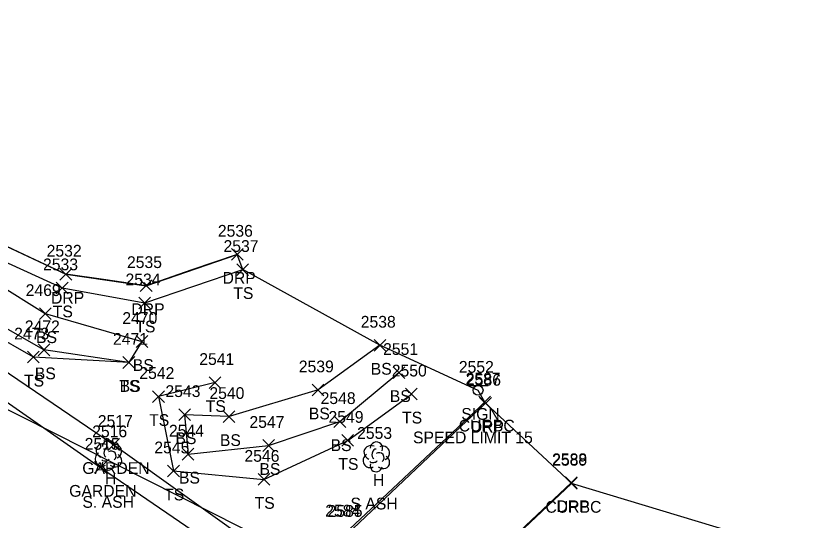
# Model space of a CAD drawing. Extents: x 1623612 to 1625808, y 621345 to 627748.
# Drawn here: x 1624561.2 to 1624694.8, y 626611.6 to 626697.4 of the extents above; entities that cross this region are included whole.
import ezdxf

# ---------------------------------------------------------------- set-up
doc = ezdxf.new("R2010")
doc.units = 0
for name, color, linetype in [('DCP', 7, 'Continuous'), ('L_A', 7, 'Continuous'), ('L_C', 7, 'Continuous'), ('L_I', 7, 'Continuous'), ('L_TIC', 7, 'Continuous'), ('LAPB', 7, 'Continuous'), ('LELB', 7, 'Continuous'), ('LSOGP', 7, 'Continuous'), ('LTD', 7, 'Continuous'), ('R_A', 7, 'Continuous'), ('R_I', 7, 'Continuous'), ('R_TIC', 7, 'Continuous'), ('RC', 7, 'Continuous'), ('RDP', 7, 'Continuous'), ('S_A', 7, 'Continuous'), ('S_C', 7, 'Continuous'), ('S_I', 7, 'Continuous'), ('SSGN', 7, 'Continuous')]:
    doc.layers.add(name, color=color, linetype=linetype)

msp = doc.modelspace()

# ---------------------------------------------------------------- linework, layer by layer
at = {"layer": 'DCP'}
msp.add_lwpolyline([(1624498.55, 626661.39), (1624711.06, 626553.97)], dxfattribs=at)
at = {"layer": 'L_TIC'}
for points in [[(1624598.82, 626653.21), (1624600.82, 626655.21)], [(1624600.82, 626653.21), (1624598.82, 626655.21)], [(1624568.13, 626650.09), (1624570.13, 626652.09)], [(1624570.13, 626650.09), (1624568.13, 626652.09)], [(1624582.16, 626647.53), (1624584.16, 626649.53)], [(1624584.16, 626647.53), (1624582.16, 626649.53)], [(1624565.25, 626645.71), (1624567.25, 626647.71)], [(1624567.25, 626645.71), (1624565.25, 626647.71)], [(1624581.7, 626640.97), (1624583.7, 626642.97)], [(1624583.7, 626640.97), (1624581.7, 626642.97)], [(1624565.04, 626639.55), (1624567.04, 626641.55)], [(1624567.04, 626639.55), (1624565.04, 626641.55)], [(1624622.15, 626640.33), (1624624.15, 626642.33)], [(1624624.15, 626640.33), (1624622.15, 626642.33)], [(1624563.23, 626638.32), (1624565.23, 626640.32)], [(1624565.23, 626638.32), (1624563.23, 626640.32)], [(1624579.46, 626637.41), (1624581.46, 626639.41)], [(1624581.46, 626637.41), (1624579.46, 626639.41)], [(1624579.46, 626637.41), (1624581.46, 626639.41)], [(1624581.46, 626637.41), (1624579.46, 626639.41)], [(1624625.39, 626635.69), (1624627.39, 626637.69)], [(1624627.39, 626635.69), (1624625.39, 626637.69)], [(1624594.13, 626633.99), (1624596.13, 626635.99)], [(1624596.13, 626633.99), (1624594.13, 626635.99)], [(1624611.63, 626632.73), (1624613.63, 626634.73)], [(1624613.63, 626632.73), (1624611.63, 626634.73)], [(1624584.51, 626631.61), (1624586.51, 626633.61)], [(1624586.51, 626631.61), (1624584.51, 626633.61)], [(1624627.51, 626632.03), (1624629.51, 626634.03)], [(1624629.51, 626632.03), (1624627.51, 626634.03)], [(1624588.95, 626628.53), (1624590.95, 626630.53)], [(1624590.95, 626628.53), (1624588.95, 626630.53)], [(1624596.51, 626628.2), (1624598.51, 626630.2)], [(1624598.51, 626628.2), (1624596.51, 626630.2)], [(1624615.33, 626627.34), (1624617.33, 626629.34)], [(1624617.33, 626627.34), (1624615.33, 626629.34)], [(1624576.88, 626623.45), (1624578.88, 626625.45)], [(1624578.88, 626623.45), (1624576.88, 626625.45)], [(1624603.23, 626623.29), (1624605.23, 626625.29)], [(1624605.23, 626623.29), (1624603.23, 626625.29)], [(1624616.68, 626624.15), (1624618.68, 626626.15)], [(1624618.68, 626624.15), (1624616.68, 626626.15)], [(1624589.54, 626621.81), (1624591.54, 626623.81)], [(1624591.54, 626621.81), (1624589.54, 626623.81)], [(1624574.65, 626619.57), (1624576.65, 626621.57)], [(1624576.65, 626619.57), (1624574.65, 626621.57)], [(1624587.06, 626618.95), (1624589.06, 626620.95)], [(1624589.06, 626618.95), (1624587.06, 626620.95)], [(1624602.44, 626617.52), (1624604.44, 626619.52)], [(1624604.44, 626617.52), (1624602.44, 626619.52)]]:
    msp.add_lwpolyline(points, dxfattribs=at)
at = {"layer": 'LAPB'}
for points in [[(1624519.69, 626684.58), (1624523.34, 626715.13), (1624488.42, 626712.03), (1624477.63, 626714.58), (1624464.93, 626721.39), (1624461.33, 626722.07), (1624457.88, 626718.13), (1624464.59, 626710.11), (1624484.4, 626690.25), (1624505.15, 626670.18), (1624528.47, 626653.34), (1624551.05, 626637.75), (1624575.65, 626620.57), (1624601.46, 626602.9)], [(1624519.69, 626684.58), (1624507.55, 626684.52), (1624497.63, 626694.65), (1624492.88, 626695.51), (1624490.14, 626692.13), (1624493.09, 626687.65), (1624508.66, 626674.45), (1624530.54, 626658.21), (1624552.68, 626641.54), (1624577.88, 626624.45), (1624603.7, 626605.97), (1624601.46, 626602.9)]]:
    msp.add_lwpolyline(points, dxfattribs=at)
at = {"layer": 'LELB'}
for points in [[(1624536.67, 626723.2), (1624539.06, 626695.14), (1624541.99, 626679.69), (1624547.43, 626666.77), (1624555.92, 626657.11), (1624569.13, 626651.09), (1624583.16, 626648.53), (1624599.82, 626654.21)], [(1624491.26, 626721.31), (1624492.07, 626719.16), (1624508.82, 626720.47), (1624530.57, 626721.74), (1624534.88, 626694.95), (1624538.16, 626676.05), (1624549.52, 626657.18), (1624566.25, 626646.71), (1624582.7, 626641.97), (1624580.46, 626638.41), (1624566.04, 626640.55), (1624551.55, 626648.76), (1624540.93, 626658.22), (1624533.96, 626671.15), (1624530.07, 626682.34), (1624528.29, 626695.83)], [(1624580.46, 626638.41), (1624564.23, 626639.32), (1624549.58, 626647.72), (1624538.33, 626656.77), (1624530.6, 626670.09), (1624527.19, 626681.4), (1624524.78, 626695.84), (1624523.34, 626715.13)], [(1624623.15, 626641.33), (1624612.63, 626633.73), (1624597.51, 626629.2), (1624589.95, 626629.53), (1624590.54, 626622.81), (1624604.23, 626624.29), (1624616.33, 626628.34), (1624626.39, 626636.69)], [(1624595.13, 626634.99), (1624585.51, 626632.61), (1624588.06, 626619.95), (1624603.44, 626618.52), (1624617.68, 626625.15), (1624628.51, 626633.03)]]:
    msp.add_lwpolyline(points, dxfattribs=at)
at = {"layer": 'LSOGP'}
msp.add_lwpolyline([(1624698.36, 626604.96), (1624655.71, 626617.85), (1624655.68, 626617.95), (1624641.1, 626631.46), (1624640.98, 626631.67), (1624639.83, 626633.66), (1624623.15, 626641.33), (1624599.82, 626654.21), (1624598.91, 626656.8), (1624591.16, 626654.14), (1624583.41, 626651.47), (1624576.58, 626652.44), (1624569.75, 626653.41), (1624563.68, 626656.25), (1624557.62, 626659.09), (1624553.68, 626663.14), (1624549.75, 626667.18), (1624546.93, 626673.49), (1624544.1, 626679.8), (1624539.06, 626695.14), (1624536.67, 626723.2)], dxfattribs=at)
at = {"layer": 'LTD'}
for p, q in [((1624576.98, 626622.69), (1624576.98, 626622.69)), ((1624576.98, 626622.69), (1624576.98, 626622.69)), ((1624622.53, 626622.41), (1624622.53, 626622.41)), ((1624622.53, 626622.41), (1624622.53, 626622.41))]:
    msp.add_line(p, q, dxfattribs=at)
for centre in [(1624577.02, 626624.12), (1624622.57, 626623.84)]:
    msp.add_arc(centre, 1.05, 335.5272, 180.9563, dxfattribs=at)
for centre, major_axis, ratio, start_param, end_param in [((1624576.18, 626623.36), (1.21, -0.51), 0.895232, 1.570796, 4.712389), ((1624576.77, 626623.15), (-0.208, -0.792), 0.645439, 3.141593, 6.283185), ((1624578.02, 626623.27), (-1.14, -0.48), 0.949671, 1.570796, 4.712389), ((1624621.73, 626623.07), (1.21, -0.51), 0.895232, 1.570796, 4.712389), ((1624623.57, 626622.99), (-1.14, -0.48), 0.949671, 1.570796, 4.712389), ((1624575.89, 626621.98), (0.58, -1.04), 0.959034, 3.141593, 6.283185), ((1624577.48, 626622.52), (-0.5, 0.667), 0.989748, 3.141593, 6.283185), ((1624577.98, 626621.86), (-1.09, 0.79), 0.841452, 1.570796, 4.712389), ((1624621.44, 626621.7), (0.58, -1.04), 0.959034, 3.141593, 6.283185), ((1624622.32, 626622.87), (-0.208, -0.792), 0.645439, 3.141593, 6.283185), ((1624623.03, 626622.24), (-0.5, 0.667), 0.989748, 3.141593, 6.283185), ((1624576.98, 626621.19), (0.26, 1.06), 0.942809, 1.570796, 4.712389), ((1624576.52, 626621.94), (-0.625, -0.083), 0.423636, 0, 3.141593), ((1624622.07, 626621.66), (-0.625, -0.083), 0.423636, 0, 3.141593), ((1624623.53, 626621.57), (-1.09, 0.79), 0.841452, 1.570796, 4.712389), ((1624622.53, 626620.91), (0.26, 1.06), 0.942809, 1.570796, 4.712389)]:
    msp.add_ellipse(centre, major_axis=major_axis, ratio=ratio, start_param=start_param, end_param=end_param, dxfattribs=at)
at = {"layer": 'R_TIC'}
for points in [[(1624597.91, 626655.8), (1624599.91, 626657.8)], [(1624599.91, 626655.8), (1624597.91, 626657.8)], [(1624568.75, 626652.41), (1624570.75, 626654.41)], [(1624570.75, 626652.41), (1624568.75, 626654.41)], [(1624582.41, 626650.47), (1624584.41, 626652.47)], [(1624584.41, 626650.47), (1624582.41, 626652.47)], [(1624639.98, 626630.67), (1624641.98, 626632.67)], [(1624641.98, 626630.67), (1624639.98, 626632.67)], [(1624640.1, 626630.46), (1624642.1, 626632.46)], [(1624642.1, 626630.46), (1624640.1, 626632.46)], [(1624654.68, 626616.95), (1624656.68, 626618.95)], [(1624656.68, 626616.95), (1624654.68, 626618.95)], [(1624654.71, 626616.85), (1624656.71, 626618.85)], [(1624656.71, 626616.85), (1624654.71, 626618.85)]]:
    msp.add_lwpolyline(points, dxfattribs=at)
at = {"layer": 'RC'}
for points in [[(1624556.22, 626591.8), (1624557.51, 626590.81), (1624585.01, 626562.27), (1624585.7, 626562.26), (1624586.31, 626562.81), (1624590.62, 626575.25), (1624594.11, 626582.77), (1624601.07, 626592.28), (1624605.9, 626598.14), (1624617.1, 626609.2), (1624640.98, 626631.67)], [(1624655.71, 626617.85), (1624631.59, 626595.03), (1624625.69, 626589.4), (1624618.54, 626581.03), (1624613.56, 626573.77), (1624609.69, 626566.13), (1624607.96, 626559.16), (1624607.72, 626545.48), (1624608.94, 626538.06), (1624609.17, 626536.98)]]:
    msp.add_lwpolyline(points, dxfattribs=at)
at = {"layer": 'RDP'}
for points in [[(1624544.1, 626679.8), (1624549.75, 626667.18), (1624557.62, 626659.09), (1624569.75, 626653.41), (1624583.41, 626651.47), (1624598.91, 626656.8)], [(1624584.71, 626562.13), (1624585.9, 626561.94), (1624586.5, 626562.61), (1624590.92, 626575.46), (1624594.34, 626582.68), (1624601.26, 626592.17), (1624606.05, 626597.93), (1624617.51, 626609.15), (1624641.1, 626631.46)], [(1624655.68, 626617.95), (1624631.39, 626595.1), (1624625.54, 626589.45), (1624618.3, 626581.17), (1624613.44, 626573.99), (1624609.42, 626566.14), (1624607.75, 626559.3), (1624607.57, 626545.47), (1624608.69, 626538.1), (1624609.17, 626536.98)]]:
    msp.add_lwpolyline(points, dxfattribs=at)
at = {"layer": 'SSGN'}
for p, q in [((1624638.21, 626634.51), (1624641.54, 626634.51)), ((1624639.85, 626633.68), (1624639.85, 626633.68))]:
    msp.add_line(p, q, dxfattribs=at)
msp.add_circle((1624639.85, 626633.68), 0.833, dxfattribs=at)

# ---------------------------------------------------------------- texts
at = {"layer": 'L_A'}
for s, p in [('TS', (1624598.23, 626649.21)), ('TS', (1624567.54, 626646.09)), ('TS', (1624581.57, 626643.53)), ('BS', (1624564.69, 626641.71)), ('BS', (1624581.14, 626636.97)), ('BS', (1624564.48, 626635.55)), ('BS', (1624621.59, 626636.33)), ('TS', (1624562.64, 626634.32)), ('TS', (1624578.87, 626633.41)), ('BS', (1624578.9, 626633.41)), ('BS', (1624624.83, 626631.69)), ('TS', (1624593.54, 626629.99)), ('BS', (1624611.07, 626628.73)), ('TS', (1624583.92, 626627.61)), ('TS', (1624626.92, 626628.03)), ('BS', (1624588.39, 626624.53)), ('BS', (1624595.95, 626624.2)), ('BS', (1624614.77, 626623.34)), ('GARDEN', (1624572.55, 626619.45)), ('BS', (1624602.67, 626619.29)), ('TS', (1624616.09, 626620.15)), ('H', (1624576.41, 626617.69)), ('BS', (1624588.99, 626617.81)), ('H', (1624621.96, 626617.41)), ('GARDEN', (1624570.32, 626615.57)), ('TS', (1624586.47, 626614.95)), ('TS', (1624601.85, 626613.52))]:
    msp.add_text(s, height=2, dxfattribs=at).set_placement(p)
at = {"layer": 'L_C'}
for s, p in [('S. ASH', (1624572.57, 626613.69)), ('S ASH', (1624618.15, 626613.41))]:
    msp.add_text(s, height=2, dxfattribs=at).set_placement(p)
at = {"layer": 'L_I'}
for s, p in [('2537', (1624596.56, 626657.21)), ('2533', (1624565.88, 626654.09)), ('2534', (1624579.9, 626651.53)), ('2469', (1624562.93, 626649.71)), ('2470', (1624579.36, 626644.97)), ('2472', (1624562.78, 626643.55)), ('2538', (1624619.89, 626644.33)), ('2473', (1624560.97, 626642.32)), ('2471', (1624577.77, 626641.41)), ('2471', (1624577.77, 626641.41)), ('2551', (1624623.69, 626639.69)), ('2541', (1624592.44, 626637.99)), ('2539', (1624609.36, 626636.73)), ('2542', (1624582.25, 626635.61)), ('2550', (1624625.17, 626636.03)), ('2543', (1624586.69, 626632.53)), ('2540', (1624594.16, 626632.2)), ('2548', (1624613.07, 626631.34)), ('2517', (1624575.19, 626627.45)), ('2547', (1624600.97, 626627.29)), ('2549', (1624614.41, 626628.15)), ('2516', (1624574.23, 626625.69)), ('2544', (1624587.28, 626625.81)), ('2553', (1624619.27, 626625.41)), ('2515', (1624572.96, 626623.57)), ('2545', (1624584.8, 626622.95)), ('2546', (1624600.12, 626621.52))]:
    msp.add_text(s, height=2, dxfattribs=at).set_placement(p)
at = {"layer": 'R_A'}
for s, p in [('DRP', (1624596.4, 626651.8)), ('DRP', (1624567.23, 626648.41)), ('DRP', (1624580.9, 626646.47)), ('CURBC', (1624636.56, 626626.67)), ('DRP', (1624638.59, 626626.46)), ('CURBC', (1624651.3, 626612.85)), ('DRP', (1624653.17, 626612.95))]:
    msp.add_text(s, height=2, dxfattribs=at).set_placement(p)
at = {"layer": 'R_I'}
for s, p in [('2536', (1624595.6, 626659.8)), ('2532', (1624566.49, 626656.41)), ('2535', (1624580.15, 626654.47)), ('2587', (1624637.72, 626634.67)), ('2586', (1624637.79, 626634.46)), ('2588', (1624652.42, 626620.95)), ('2589', (1624652.45, 626620.85)), ('2584', (1624613.85, 626612.2)), ('2585', (1624614.25, 626612.15))]:
    msp.add_text(s, height=2, dxfattribs=at).set_placement(p)
at = {"layer": 'S_A'}
msp.add_text('SIGN', height=2, dxfattribs=at).set_placement((1624636.99, 626628.66))
at = {"layer": 'S_C'}
msp.add_text('SPEED LIMIT 15', height=2, dxfattribs=at).set_placement((1624628.78, 626624.66))
at = {"layer": 'S_I'}
msp.add_text('2552', height=2, dxfattribs=at).set_placement((1624636.57, 626636.66))

doc.saveas('drawing.dxf')
